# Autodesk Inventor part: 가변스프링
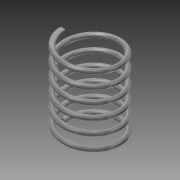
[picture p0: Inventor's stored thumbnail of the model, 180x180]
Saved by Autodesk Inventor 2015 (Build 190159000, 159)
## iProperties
Created: 2016-02
Part Number: 가변스프링
Material: 스테인레스 스틸
Document SubType Name: Modeling
Designer: Administrator
Density: 8 g/cm^3
Appearance: 반연마
Mass: 84.1995 g
Surface Area: 106.448 cm^2
Volume: 10.5249 cm^3
Author: Administrator
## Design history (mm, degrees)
sketch "스케치1"
  geometry: L1 (0, 0)-(22.5, 0); L2 (22.5, 0)-(22.5, 67.25); L3 (22.5, 67.25)-(0, 67.25); L4 (0, 67.25)-(0, 0); C1 r 2 at (22.5, 0)
  constraints: 8 end point, 2 parallel, 1 centre point, 1 coincident, 1 horizontal, 1 perpendicular
  dimensions: "d0" = 45 diameter of L2 L4; "d1" = 67.25 distance between parallel lines of L1 L3 (derived); "d2" = 4 diameter of C1
feature "코일1" sketch "스케치1" pitch "d3" = 10; turns "d5" = 6; dims "d4" = 67.25 (= d1), "d6" = 0, angle "d7" = 90 deg, angle "d8" = 90 deg, "d9" = 0, "d10" = 0
sketch "스케치2"
  geometry: L1 (-20.5, 0)-(-24.5, 0) reference; 1 further point
  constraints: 1 horizontal alignment
extrude "돌출1" cut sketch "스케치2" distance "d11" = 10; taper "d12" = 0 deg
node "작업 평면1"
sketch "스케치3"
  geometry: L1 (20.5, 0)-(24.5, 0) reference; 1 further point
  constraints: 1 horizontal alignment
extrude "돌출2" cut sketch "스케치3" distance "d13" = 10; taper "d14" = 0 deg
node "솔리드1"
node "절단 모서리 투영1"
node "절단 모서리 투영2"
